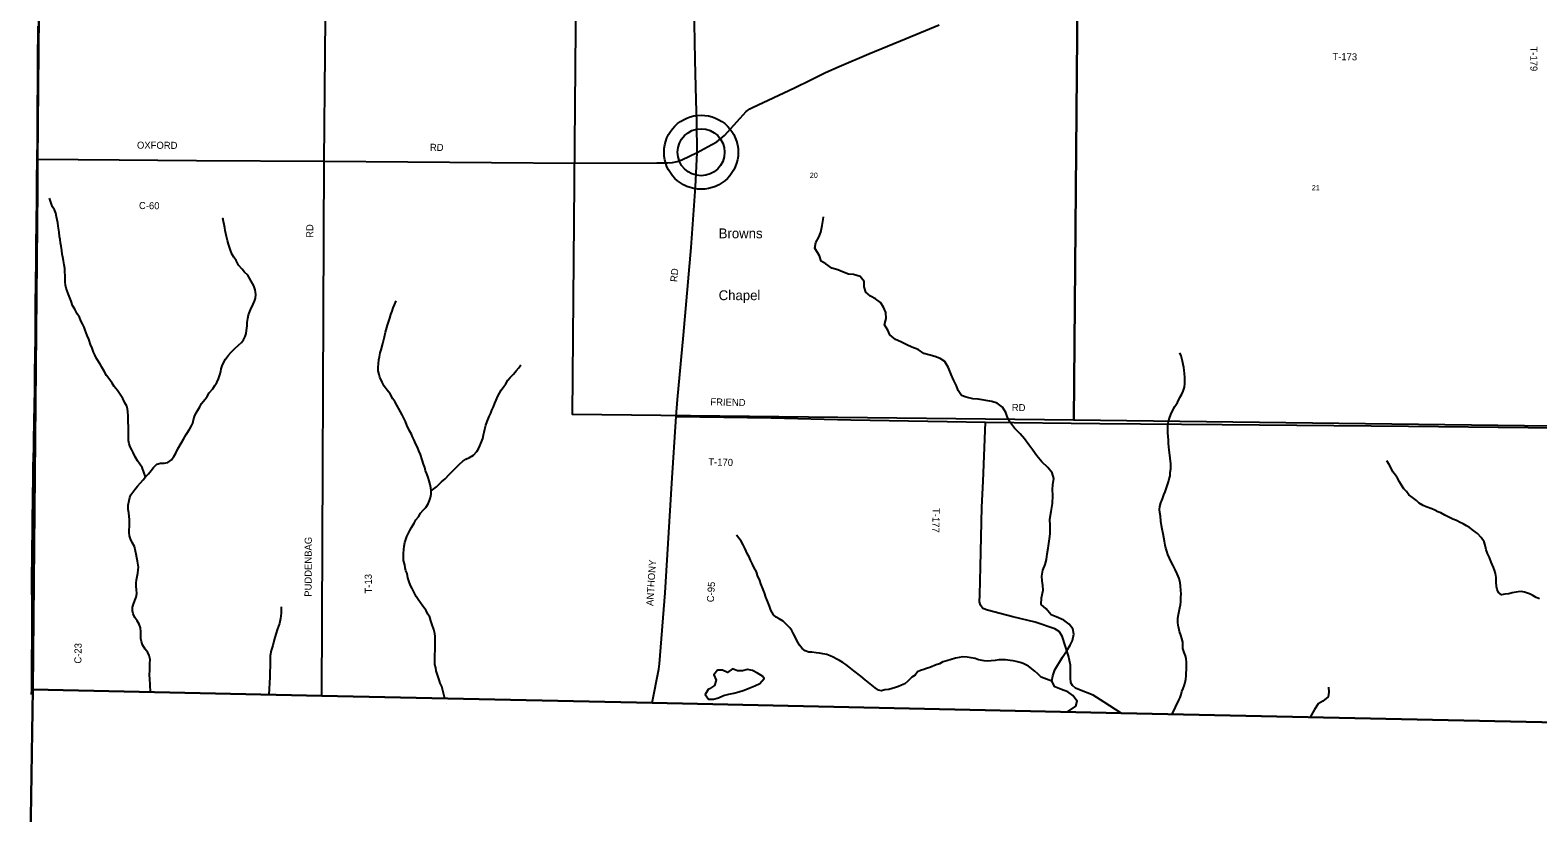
# Model space of a CAD drawing. Extents: x 1312308 to 1684953, y 460642 to 865172.
# Drawn here: x 1410763 to 1426746, y 583725 to 592024 of the extents above; entities that cross this region are included whole.
import ezdxf

# ---------------------------------------------------------------- set-up
doc = ezdxf.new("R2010")
doc.units = 0
for name, color, linetype in [('GM_X_Adjacent_County', 7, 'Continuous'), ('GM_X_County', 7, 'Continuous'), ('GM_X_County_Road', 7, 'Continuous'), ('GM_X_County_Road_Text', 7, 'Continuous'), ('GM_X_Minor_Lake', 7, 'Continuous'), ('GM_X_Minor_River', 7, 'Continuous'), ('GM_X_Section', 7, 'Continuous'), ('GM_X_Section_Text', 7, 'Continuous'), ('GM_X_Township', 7, 'Continuous'), ('GM_X_Township_Road', 7, 'Continuous'), ('GM_X_Township_Road_Text', 7, 'Continuous'), ('GM_X_Unincorporated', 7, 'Continuous'), ('GM_X_Unincorporated_Location', 7, 'Continuous'), ('GM_X_Unincorporated_Text', 7, 'Continuous')]:
    doc.layers.add(name, color=color, linetype=linetype)

msp = doc.modelspace()

# ---------------------------------------------------------------- linework, layer by layer
at = {"layer": 'GM_X_Adjacent_County'}
for points in [[(1411211, 633565), (1411180, 628296), (1411163, 625648), (1411153, 624951), (1411095, 617624), (1411090, 617033), (1411020, 612269), (1411018, 611981), (1410999, 609618), (1410998, 609429), (1410982, 607392), (1410977, 606751), (1410955, 603992), (1410939, 601893), (1410907, 597962), (1410895, 596474), (1410841, 590631), (1410839, 590333), (1410790, 585032), (1410763, 583224)], [(1410763, 583224), (1410790, 585032), (1413856, 584966), (1417357, 584890), (1422329, 584782), (1427118, 584678), (1429424, 584629), (1433762, 584535), (1437664, 584451), (1440214, 584396), (1442866, 584339), (1442856, 582398)]]:
    msp.add_lwpolyline(points, dxfattribs=at)
at = {"layer": 'GM_X_County'}
msp.add_lwpolyline([(1458988, 584007), (1454534, 584099), (1454383, 584102), (1453707, 584116), (1452022, 584152), (1450736, 584179), (1450715, 584179), (1442866, 584339), (1440214, 584396), (1437664, 584451), (1433762, 584535), (1429424, 584629), (1427118, 584678), (1422329, 584782), (1417357, 584890), (1413856, 584966), (1410790, 585032), (1410839, 590333), (1410841, 590631), (1410895, 596474), (1410907, 597962), (1410939, 601893), (1410955, 603992), (1410977, 606751)], dxfattribs=at)
at = {"layer": 'GM_X_County_Road'}
for points in [[(1417357, 584890), (1417427, 585247), (1417433, 585306), (1417493, 586057), (1417566, 587221), (1417613, 587927), (1417626, 588108), (1417689, 588788), (1417770, 589720), (1417816, 590362), (1417834, 590727), (1417832, 591043), (1417824, 591283), (1417811, 591710), (1417802, 592288)], [(1410837, 590655), (1411707, 590647), (1412525, 590640), (1413880, 590635), (1416542, 590614), (1417407, 590616), (1417519, 590616), (1417571, 590621), (1417621, 590630), (1417671, 590647), (1417834, 590727), (1417991, 590811), (1418041, 590841), (1418124, 590908), (1418289, 591092), (1418352, 591161), (1418392, 591188), (1418421, 591205), (1418865, 591413), (1419039, 591497), (1419194, 591574), (1419341, 591638), (1419655, 591771), (1420048, 591934), (1420399, 592081)], [(1410837, 590655), (1410838, 590729), (1410839, 590783), (1410840, 590920), (1410841, 591101), (1410842, 591219), (1410842, 591322), (1410843, 591352), (1410843, 591382), (1410843, 591514), (1410844, 591631), (1410845, 591842), (1410846, 591902), (1410847, 592013), (1410848, 592065)], [(1410833, 590349), (1410833, 590367), (1410834, 590448), (1410835, 590502), (1410836, 590593), (1410837, 590655)], [(1410787, 586722), (1410788, 586778), (1410789, 586877), (1410790, 587010), (1410791, 587132), (1410793, 587219), (1410794, 587305), (1410796, 587411), (1410797, 587480), (1410800, 587610), (1410802, 587717), (1410805, 587831), (1410806, 587901), (1410808, 588023), (1410809, 588066), (1410811, 588190), (1410812, 588287), (1410813, 588346), (1410814, 588423), (1410816, 588556), (1410818, 588781), (1410818, 588891), (1410819, 589003), (1410820, 589128), (1410823, 589329), (1410824, 589435), (1410825, 589492), (1410826, 589594), (1410827, 589723), (1410828, 589812), (1410829, 589916), (1410830, 590049), (1410832, 590173), (1410832, 590228), (1410833, 590349)], [(1410777, 584979), (1410780, 585032), (1410780, 585082), (1410781, 585193), (1410782, 585308), (1410782, 585395), (1410783, 585527), (1410783, 585638), (1410784, 585789), (1410783, 585893), (1410783, 585992), (1410782, 586079), (1410782, 586122), (1410782, 586288), (1410783, 586379), (1410785, 586562), (1410787, 586677), (1410787, 586722)]]:
    msp.add_lwpolyline(points, dxfattribs=at)
at = {"layer": 'GM_X_Minor_Lake'}
for points in [[(1417952, 585032), (1417919, 584980), (1417954, 584929), (1418008, 584930), (1418059, 584943), (1418113, 584968), (1418170, 584984), (1418224, 584993), (1418274, 585008), (1418331, 585027), (1418392, 585050), (1418446, 585070), (1418497, 585095), (1418544, 585148), (1418525, 585175)], [(1418525, 585175), (1418473, 585206), (1418422, 585234), (1418368, 585245), (1418313, 585230), (1418263, 585229), (1418210, 585252), (1418155, 585214), (1418103, 585237), (1418049, 585238), (1418012, 585187), (1418037, 585132), (1418017, 585076), (1417965, 585041), (1417952, 585032)]]:
    msp.add_lwpolyline(points, dxfattribs=at)
at = {"layer": 'GM_X_Minor_River'}
for points in [[(1411985, 587286), (1411950, 587385), (1411927, 587421), (1411902, 587458), (1411877, 587499), (1411854, 587544), (1411839, 587574), (1411822, 587605), (1411812, 587637), (1411807, 587673), (1411805, 587727), (1411805, 587789), (1411804, 587829), (1411803, 587861), (1411803, 587891), (1411803, 587935), (1411798, 587976), (1411795, 588008), (1411786, 588038), (1411768, 588073), (1411744, 588117), (1411711, 588172), (1411690, 588203), (1411655, 588246), (1411632, 588282), (1411597, 588331), (1411572, 588362), (1411547, 588407), (1411521, 588450), (1411506, 588482), (1411467, 588541), (1411448, 588580), (1411433, 588610), (1411420, 588653), (1411403, 588689), (1411383, 588746), (1411368, 588786), (1411347, 588843), (1411334, 588875), (1411317, 588910), (1411300, 588942), (1411285, 588979), (1411262, 589015), (1411235, 589064), (1411212, 589103), (1411196, 589149), (1411183, 589186), (1411170, 589220), (1411158, 589250), (1411145, 589287), (1411138, 589321), (1411135, 589355), (1411133, 589423), (1411132, 589459), (1411131, 589497), (1411124, 589534), (1411115, 589578), (1411109, 589616), (1411103, 589648), (1411098, 589686), (1411092, 589733), (1411085, 589769), (1411080, 589805), (1411075, 589835), (1411070, 589881), (1411060, 589946), (1411057, 589982), (1411048, 590014), (1411042, 590044), (1411035, 590083), (1411020, 590117), (1411001, 590150), (1410988, 590180), (1410977, 590210), (1410968, 590243)], [(1413042, 588776), (1413053, 588809), (1413058, 588839), (1413063, 588887), (1413064, 588925), (1413069, 588967), (1413076, 589005), (1413098, 589058), (1413128, 589120), (1413142, 589151), (1413151, 589183), (1413156, 589221), (1413148, 589269), (1413135, 589312), (1413104, 589363), (1413087, 589393), (1413070, 589426), (1413035, 589459), (1413010, 589489), (1412971, 589532), (1412946, 589581), (1412923, 589616), (1412906, 589646), (1412891, 589681), (1412876, 589721), (1412867, 589756), (1412856, 589794), (1412845, 589836), (1412838, 589866), (1412831, 589899), (1412826, 589929), (1412819, 589963), (1412811, 589995), (1412806, 590025), (1412806, 590024)], [(1412809, 589982), (1412809, 589981)], [(1419145, 589881), (1419159, 589953), (1419169, 590017), (1419174, 590045)], [(1421759, 584796), (1421848, 584855), (1421862, 584909), (1421818, 584968), (1421763, 585008), (1421697, 585034), (1421624, 585062), (1421594, 585122), (1421604, 585179), (1421624, 585241), (1421706, 585375), (1421750, 585438), (1421788, 585503), (1421812, 585554), (1421826, 585620), (1421817, 585676), (1421779, 585727), (1421722, 585767), (1421639, 585802), (1421585, 585825), (1421535, 585889), (1421482, 585933), (1421486, 586003), (1421501, 586085), (1421500, 586135), (1421492, 586185), (1421487, 586235), (1421499, 586297), (1421523, 586357), (1421537, 586410), (1421545, 586472), (1421555, 586532), (1421570, 586630), (1421575, 586684), (1421576, 586772), (1421574, 586838), (1421588, 586920), (1421601, 587006), (1421604, 587090), (1421600, 587154), (1421603, 587204), (1421615, 587270), (1421597, 587329), (1421552, 587386), (1421488, 587448), (1421434, 587512), (1421392, 587571), (1421351, 587627), (1421303, 587692), (1421258, 587744), (1421198, 587802), (1421154, 587859), (1421123, 587918), (1421105, 587971), (1421072, 588026), (1421014, 588070), (1420958, 588087), (1420814, 588112), (1420756, 588113), (1420687, 588132), (1420635, 588151), (1420600, 588202), (1420582, 588253), (1420552, 588316), (1420525, 588373), (1420497, 588444), (1420461, 588509), (1420410, 588543), (1420353, 588564), (1420291, 588580), (1420237, 588594), (1420176, 588636), (1420111, 588664), (1420058, 588688), (1419994, 588720), (1419935, 588743), (1419878, 588793), (1419856, 588844), (1419821, 588899), (1419837, 588965), (1419835, 589031), (1419811, 589086), (1419776, 589137), (1419725, 589175), (1419672, 589204), (1419621, 589246), (1419603, 589303), (1419605, 589357), (1419562, 589410), (1419493, 589432), (1419439, 589438), (1419375, 589462), (1419324, 589483), (1419260, 589501), (1419199, 589547), (1419148, 589575), (1419130, 589631), (1419080, 589711), (1419092, 589773), (1419122, 589830), (1419145, 589881)], [(1414705, 587946), (1414690, 587977), (1414669, 588015), (1414650, 588046), (1414627, 588085), (1414608, 588115), (1414581, 588168), (1414548, 588205), (1414517, 588250), (1414496, 588290), (1414470, 588343), (1414461, 588373), (1414452, 588410), (1414451, 588452), (1414454, 588486), (1414459, 588528), (1414466, 588561), (1414475, 588603), (1414484, 588635), (1414502, 588703), (1414518, 588772), (1414531, 588822), (1414551, 588894), (1414564, 588937), (1414575, 588971), (1414588, 589009), (1414600, 589045), (1414610, 589078), (1414625, 589112), (1414643, 589152)], [(1412037, 585007), (1412031, 585148), (1412028, 585180), (1412030, 585244), (1412033, 585276), (1412032, 585308), (1412035, 585352), (1412026, 585394), (1412009, 585425), (1411982, 585461), (1411953, 585508), (1411942, 585541), (1411937, 585571), (1411936, 585603), (1411937, 585645), (1411932, 585687), (1411919, 585725), (1411898, 585760), (1411871, 585795), (1411854, 585835), (1411847, 585866), (1411846, 585906), (1411857, 585939), (1411872, 585977), (1411885, 586011), (1411892, 586049), (1411890, 586093), (1411886, 586125), (1411887, 586161), (1411890, 586195), (1411904, 586267), (1411909, 586300), (1411910, 586330), (1411900, 586395), (1411895, 586429), (1411888, 586469), (1411881, 586501), (1411868, 586550), (1411845, 586593), (1411828, 586631), (1411817, 586663), (1411812, 586696), (1411813, 586726), (1411816, 586762), (1411815, 586800), (1411816, 586836), (1411813, 586866), (1411810, 586906), (1411803, 586942), (1411802, 586986), (1411812, 587038), (1411821, 587068), (1411831, 587098), (1411873, 587153), (1411902, 587188), (1411931, 587225), (1411960, 587256), (1411985, 587286), (1412016, 587321), (1412045, 587356), (1412070, 587388), (1412105, 587423), (1412145, 587434), (1412183, 587433), (1412222, 587440), (1412260, 587467), (1412285, 587502), (1412306, 587538), (1412330, 587583), (1412363, 587646), (1412389, 587686), (1412418, 587737), (1412454, 587798), (1412473, 587828), (1412488, 587857), (1412496, 587891), (1412506, 587929), (1412521, 587966), (1412539, 587996), (1412560, 588029), (1412579, 588065), (1412617, 588110), (1412638, 588140), (1412661, 588177), (1412698, 588220), (1412721, 588255), (1412740, 588287), (1412759, 588325), (1412774, 588368), (1412783, 588404), (1412788, 588434), (1412797, 588464), (1412816, 588503), (1412835, 588535), (1412864, 588576), (1412895, 588611), (1412932, 588648), (1412971, 588683), (1413004, 588711), (1413023, 588740), (1413042, 588776)], [(1422871, 584772), (1422941, 584918), (1422956, 584948), (1422966, 584981), (1422971, 585011), (1422986, 585043), (1422995, 585073), (1423006, 585107), (1423013, 585144), (1423018, 585178), (1423019, 585208), (1423022, 585240), (1423021, 585274), (1423020, 585321), (1423017, 585357), (1423010, 585391), (1422997, 585425), (1422984, 585466), (1422983, 585502), (1422982, 585536), (1422971, 585574), (1422962, 585610), (1422949, 585647), (1422940, 585683), (1422933, 585713), (1422930, 585746), (1422931, 585788), (1422936, 585827), (1422945, 585865), (1422950, 585899), (1422957, 585931), (1422960, 585961), (1422963, 586007), (1422964, 586047), (1422963, 586083), (1422959, 586133), (1422953, 586164), (1422943, 586210), (1422924, 586258), (1422903, 586305), (1422880, 586348), (1422859, 586386), (1422843, 586427), (1422825, 586463), (1422812, 586500), (1422801, 586530), (1422794, 586564), (1422787, 586607), (1422774, 586685), (1422765, 586733), (1422758, 586772), (1422751, 586816), (1422745, 586870), (1422738, 586910), (1422735, 586940), (1422740, 586974), (1422751, 587012), (1422766, 587054), (1422781, 587097), (1422794, 587129), (1422805, 587159), (1422816, 587193), (1422829, 587234), (1422838, 587268), (1422847, 587300), (1422850, 587332), (1422855, 587372), (1422856, 587424), (1422850, 587486), (1422845, 587516), (1422838, 587569), (1422835, 587607), (1422830, 587645), (1422829, 587677), (1422826, 587717), (1422823, 587755), (1422823, 587793), (1422824, 587833), (1422829, 587873), (1422840, 587911), (1422855, 587949), (1422878, 587996), (1422897, 588032), (1422925, 588077), (1422952, 588130), (1422971, 588164), (1422986, 588195), (1422999, 588239), (1423004, 588277), (1423005, 588307), (1423004, 588341), (1422999, 588383), (1422996, 588418), (1422993, 588448), (1422986, 588480), (1422979, 588514), (1422966, 588571), (1422951, 588601)], [(1415013, 587139), (1415072, 587183), (1415124, 587234), (1415161, 587267), (1415206, 587314), (1415245, 587353), (1415315, 587423), (1415350, 587454), (1415383, 587476), (1415421, 587491), (1415462, 587518), (1415499, 587555), (1415516, 587584), (1415529, 587618), (1415548, 587659), (1415561, 587695), (1415570, 587733), (1415575, 587763), (1415582, 587793), (1415593, 587836), (1415606, 587876), (1415628, 587926), (1415645, 587963), (1415658, 587993), (1415673, 588029), (1415690, 588070), (1415703, 588102), (1415720, 588144), (1415739, 588175), (1415756, 588205), (1415783, 588244), (1415804, 588275), (1415825, 588311), (1415852, 588342), (1415887, 588377), (1415916, 588411), (1415943, 588444), (1415966, 588475)], [(1415158, 584939), (1415127, 585063), (1415110, 585100), (1415097, 585136), (1415088, 585166), (1415079, 585199), (1415068, 585229), (1415063, 585261), (1415054, 585299), (1415053, 585331), (1415058, 585520), (1415057, 585556), (1415058, 585596), (1415053, 585628), (1415042, 585668), (1415026, 585719), (1415009, 585761), (1415000, 585798), (1414979, 585830), (1414960, 585871), (1414927, 585916), (1414902, 585950), (1414875, 585987), (1414856, 586018), (1414839, 586054), (1414812, 586103), (1414795, 586137), (1414780, 586176), (1414767, 586218), (1414760, 586261), (1414747, 586291), (1414738, 586323), (1414735, 586355), (1414720, 586402), (1414719, 586444), (1414720, 586476), (1414723, 586516), (1414728, 586554), (1414735, 586590), (1414744, 586623), (1414755, 586655), (1414770, 586685), (1414787, 586718), (1414806, 586752), (1414833, 586795), (1414850, 586833), (1414879, 586864), (1414900, 586904), (1414929, 586933), (1414956, 586964), (1414981, 587002), (1414996, 587037), (1415007, 587069), (1415014, 587103), (1415013, 587139), (1415010, 587171), (1415003, 587207), (1414992, 587246), (1414981, 587280), (1414968, 587320), (1414955, 587353), (1414946, 587385), (1414933, 587422), (1414918, 587468), (1414902, 587524), (1414883, 587565), (1414868, 587603), (1414849, 587640), (1414834, 587676), (1414817, 587711), (1414804, 587741), (1414786, 587776), (1414756, 587837), (1414743, 587875), (1414724, 587910), (1414705, 587946)], [(1426762, 585994), (1426728, 586009), (1426693, 586028), (1426659, 586047), (1426604, 586066), (1426570, 586073), (1426536, 586070), (1426473, 586056), (1426439, 586048), (1426395, 586042), (1426361, 586038), (1426329, 586061), (1426316, 586092), (1426309, 586124), (1426304, 586170), (1426304, 586220), (1426299, 586264), (1426288, 586297), (1426275, 586327), (1426252, 586382), (1426232, 586432), (1426213, 586475), (1426200, 586515), (1426191, 586550), (1426178, 586600), (1426145, 586643), (1426106, 586686), (1426069, 586715), (1426022, 586752), (1425989, 586769), (1425955, 586788), (1425923, 586803), (1425884, 586826), (1425846, 586839), (1425815, 586854), (1425759, 586882), (1425716, 586905), (1425686, 586918), (1425653, 586935), (1425623, 586947), (1425562, 586969), (1425532, 586982), (1425489, 587009), (1425459, 587038), (1425418, 587067), (1425379, 587098), (1425352, 587131), (1425325, 587162), (1425300, 587200), (1425281, 587235), (1425258, 587274), (1425238, 587306), (1425209, 587339), (1425190, 587379), (1425169, 587420), (1425145, 587459)], [(1421594, 585122), (1421479, 585163), (1421444, 585198), (1421415, 585227), (1421346, 585279), (1421289, 585307), (1421259, 585318), (1421216, 585331), (1421184, 585338), (1421152, 585340), (1421102, 585346), (1421068, 585347), (1421032, 585346), (1420994, 585341), (1420951, 585338), (1420915, 585333), (1420875, 585338), (1420818, 585349), (1420782, 585360), (1420738, 585368), (1420698, 585377), (1420652, 585378), (1420610, 585373), (1420572, 585364), (1420527, 585351), (1420481, 585338), (1420440, 585325), (1420404, 585306), (1420369, 585293), (1420299, 585267), (1420266, 585256), (1420236, 585245), (1420202, 585236), (1420171, 585221), (1420144, 585185), (1420111, 585162), (1420066, 585121), (1420035, 585094), (1420001, 585077), (1419968, 585064), (1419936, 585055), (1419902, 585045), (1419865, 585034), (1419825, 585028), (1419789, 585020), (1419755, 585027), (1419720, 585052), (1419669, 585092), (1419614, 585137), (1419569, 585173), (1419494, 585231), (1419442, 585274), (1419410, 585297), (1419377, 585320), (1419343, 585339), (1419314, 585354), (1419276, 585377), (1419244, 585390), (1419207, 585403), (1419167, 585412), (1419131, 585417), (1419097, 585422), (1419051, 585427), (1419017, 585430), (1418980, 585443), (1418948, 585468), (1418919, 585504), (1418892, 585553), (1418875, 585584), (1418854, 585624), (1418837, 585657), (1418818, 585687), (1418785, 585720), (1418744, 585758), (1418703, 585781), (1418673, 585801), (1418644, 585824), (1418615, 585875), (1418600, 585916), (1418578, 585968), (1418563, 586011), (1418546, 586057), (1418525, 586112), (1418509, 586154), (1418500, 586189), (1418475, 586243), (1418464, 586280), (1418435, 586329), (1418420, 586361), (1418401, 586404), (1418384, 586438), (1418369, 586469), (1418339, 586533), (1418320, 586568), (1418299, 586607), (1418276, 586637), (1418251, 586670)], [(1413423, 585911), (1413422, 585843), (1413416, 585785), (1413405, 585731), (1413384, 585675), (1413367, 585621), (1413349, 585558), (1413336, 585500), (1413319, 585446), (1413307, 585388), (1413308, 585334), (1413307, 585278), (1413302, 585219), (1413304, 585165), (1413292, 584980)], [(1424528, 585058), (1424529, 585004), (1424525, 584954), (1424468, 584909), (1424416, 584880), (1424378, 584821), (1424331, 584740)], [(1415174, 584887), (1415174, 584887)]]:
    msp.add_lwpolyline(points, dxfattribs=at)
at = {"layer": 'GM_X_Section'}
for points in [[(1416559, 593267), (1421873, 593189), (1421827, 587888), (1416514, 587948)], [(1421873, 593189), (1427213, 593108), (1427165, 587821), (1421827, 587888)]]:
    msp.add_lwpolyline(points, close=True, dxfattribs=at)
at = {"layer": 'GM_X_Township'}
msp.add_lwpolyline([(1427118, 584678), (1422329, 584782), (1417357, 584890), (1413856, 584966), (1410790, 585032), (1410839, 590333), (1410841, 590631), (1410895, 596474), (1410907, 597962), (1410939, 601893), (1410955, 603992), (1410977, 606751)], dxfattribs=at)
at = {"layer": 'GM_X_Township_Road'}
for points in [[(1413880, 590635), (1413900, 592913), (1413914, 594273), (1413930, 595757), (1413949, 596464), (1413954, 597420)], [(1413856, 584966), (1413880, 590635)], [(1417613, 587927), (1418617, 587913), (1419464, 587892), (1420889, 587867), (1422103, 587853), (1423398, 587843), (1425376, 587824), (1426645, 587809)], [(1422329, 584782), (1422149, 584899), (1422033, 584974), (1421887, 585030), (1421846, 585047), (1421813, 585075), (1421797, 585104), (1421791, 585156), (1421790, 585292), (1421770, 585390), (1421703, 585597), (1421670, 585646), (1421626, 585677), (1421416, 585747), (1421180, 585805), (1420913, 585874), (1420861, 585892), (1420837, 585927), (1420828, 585961), (1420831, 586037), (1420837, 586335), (1420853, 586967), (1420866, 587242), (1420889, 587867)], [(1426645, 587809), (1427164, 587803), (1429021, 587784), (1430506, 587763)]]:
    msp.add_lwpolyline(points, dxfattribs=at)
at = {"layer": 'GM_X_Unincorporated'}
for radius in [393, 249]:
    msp.add_circle((1417876, 590729), radius, dxfattribs=at)
at = {"layer": 'GM_X_Unincorporated_Location'}
msp.add_line((1417876, 590729), (1417876, 590729), dxfattribs=at)

# ---------------------------------------------------------------- texts
at = {"layer": 'GM_X_County_Road_Text'}
for s, rotation, p in [('OXFORD', 359.6671, (1411895, 590767)), ('RD', 359.5064, (1415000, 590744)), ('C-60', 359.3157, (1411916, 590127)), ('RD', 85.196, (1417623, 589351)), ('ANTHONY', 86.4148, (1417368, 585917)), ('C-95', 86.2309, (1418010, 585956)), ('C-23', 89.4091, (1411306, 585307))]:
    msp.add_text(s, height=75, rotation=rotation, dxfattribs=at).set_placement(p)
at = {"layer": 'GM_X_Section_Text'}
for s, p in [('20', (1419028, 590457)), ('21', (1424349, 590325))]:
    msp.add_text(s, height=55.3, rotation=0, dxfattribs=at).set_placement(p)
at = {"layer": 'GM_X_Township_Road_Text'}
for s, rotation, p in [('T-173', 359.1698, (1424568, 591707)), ('T-179', 270, (1426667, 591850)), ('RD', 90, (1413764, 589821)), ('FRIEND', 358.6721, (1417973, 588046)), ('RD', 359.5054, (1421169, 587985)), ('T-170', 358.5961, (1417951, 587409)), ('T-177', 268.8768, (1420331, 586958)), ('PUDDENBAG', 89.777, (1413746, 586016)), ('T-13', 90, (1414385, 586051))]:
    msp.add_text(s, height=75, rotation=rotation, dxfattribs=at).set_placement(p)
at = {"layer": 'GM_X_Unincorporated_Text'}
for s, p in [('Browns', (1418062, 589817)), ('Chapel', (1418062, 589161))]:
    msp.add_text(s, height=104.3, rotation=0, dxfattribs=at).set_placement(p)

doc.saveas('drawing.dxf')
